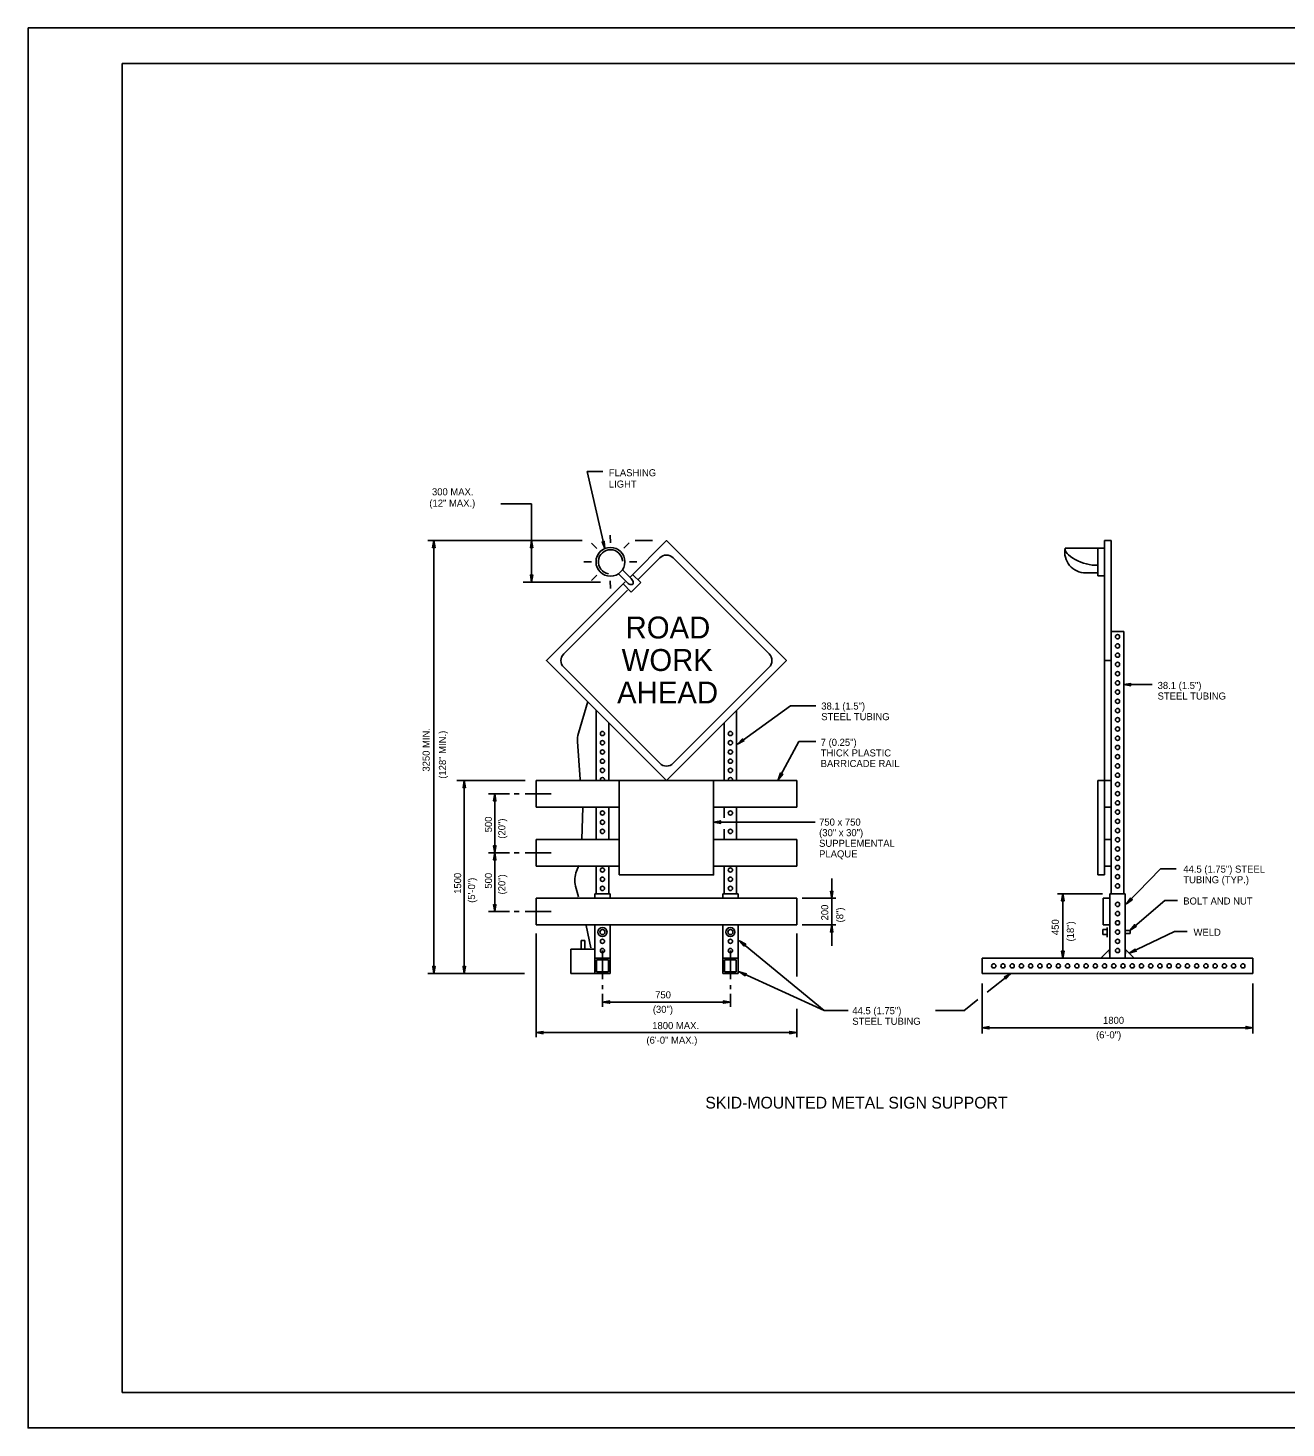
# Model space of a CAD drawing. Extents: x 641885 to 642790, y 293700 to 294294.
# Drawn here: x 641885 to 642419, y 293700 to 294294 of the extents above; entities that cross this region are included whole.
import ezdxf

# ---------------------------------------------------------------- set-up
doc = ezdxf.new("R2010")
doc.units = 0
for name, color, linetype in [('1', 7, 'Continuous'), ('2', 7, 'Continuous'), ('3', 7, 'Continuous'), ('PLT-BNDY', 7, 'Continuous')]:
    doc.layers.add(name, color=color, linetype=linetype)

# ---------------------------------------------------------------- blocks, each defined once
blk = doc.blocks.new('RARROW')
at = {"layer": '3'}
blk.add_lwpolyline([(-2.2695, 0.285), (-2.184875, 0.12075), (0, 0), (-2.2695, 0.285), (-2.38575, 0.384625), (0, 0), (-2.183125, -0.108), (-2.262875, -0.2705), (0, 0), (-2.38575, -0.379125), (-2.262875, -0.2705)], dxfattribs=at)

msp = doc.modelspace()

# ---------------------------------------------------------------- linework, layer by layer
at = {"layer": '1'}
for p, q in [((641925.31, 294278.63), (642711.31, 294278.63)), ((641925.31, 294278.63), (641925.31, 293714.63)), ((642711.31, 293714.63), (641925.31, 293714.63)), ((641925.31, 293714.63), (642511.31, 293714.63))]:
    msp.add_line(p, q, dxfattribs=at)
at = {"layer": '2'}
for p, q in [((642122.46, 294105.39), (642129.1, 294105.39)), ((642122.46, 294105.39), (642129.94, 294072.78)), ((642085.79, 294091.69), (642098.9, 294091.69)), ((642098.9, 294091.69), (642098.9, 294058.57)), ((642132.3, 294075.22), (642132.28, 294078.43)), ((642054.87, 294076.13), (642120.37, 294076.13)), ((642057.44, 293892.46), (642057.44, 294076.13)), ((642126.6, 294072.84), (642124.32, 294075.09)), ((642138.01, 294072.88), (642140.27, 294075.15)), ((642142.84, 294076.13), (642150.19, 294076.13)), ((642325.24, 294072.95), (642341.94, 294072.95)), ((642339.12, 294072.95), (642339.12, 294061.13)), ((642341.94, 294076.13), (642341.94, 293974.31)), ((642341.94, 294076.13), (642344.76, 294076.13)), ((642344.76, 294076.13), (642344.76, 293974.31)), ((642124.25, 294067.12), (642121.05, 294067.11)), ((642140.4, 294067.18), (642143.6, 294067.19)), ((642153.27, 294068.8), (642144.17, 294059.69)), ((642199.67, 294028.05), (642158.92, 294068.8)), ((642126.56, 294061.44), (642124.31, 294059.17)), ((642139.37, 294058.38), (642135.7, 294062.06)), ((642141.1, 294060.1), (642137.42, 294063.78)), ((642145.17, 294058.29), (642141.71, 294061.75)), ((642333.91, 294062.46), (642339.12, 294062.46)), ((642339.12, 294061.13), (642341.94, 294061.13)), ((642095.3, 294058.57), (642128.15, 294058.57)), ((642139.64, 294055.17), (642112.52, 294028.05)), ((642132.29, 294059.04), (642132.3, 294055.84)), ((642141.18, 294054.31), (642137.73, 294057.77)), ((642141.18, 294054.31), (642145.17, 294058.29)), ((642344.76, 294037.6), (642350.06, 294037.6)), ((642350.06, 294037.6), (642350.06, 293926.28)), ((642341.94, 294025.22), (642344.76, 294025.22)), ((642112.52, 294022.39), (642153.27, 293981.65)), ((642158.92, 293981.65), (642199.67, 294022.39)), ((642350.06, 294015.06), (642362.08, 294015.06)), ((642122.69, 294007.93), (642118.76, 293994.37)), ((642126.31, 294004.1), (642126.31, 293974.31)), ((642185.88, 294004.1), (642185.88, 293974.31)), ((642208.67, 294005.98), (642186.27, 293989.8)), ((642208.67, 294005.98), (642219.48, 294005.98)), ((642131.61, 293998.79), (642131.61, 293974.31)), ((642180.58, 293998.79), (642180.58, 293974.31)), ((642118.39, 293990.87), (642119.53, 293974.79)), ((642212.27, 293990.85), (642203.55, 293974.67)), ((642212.27, 293990.85), (642219.44, 293990.85)), ((642067.19, 293974.31), (642096.15, 293974.31)), ((642070.37, 293892.46), (642070.37, 293974.31)), ((642100.79, 293974.31), (642136.1, 293974.31)), ((642100.79, 293974.31), (642100.79, 293963)), ((642211.4, 293974.31), (642176.1, 293974.31)), ((642211.4, 293974.31), (642211.4, 293963)), ((642339.12, 293974.31), (642344.76, 293974.31)), ((642339.12, 293974.31), (642339.12, 293934.31)), ((642341.94, 293974.31), (642341.94, 293934.31)), ((642344.76, 293974.31), (642344.76, 293926.28)), ((642089.48, 293968.66), (642080.61, 293968.66)), ((642083.3, 293943.69), (642083.3, 293968.66)), ((642093.67, 293968.66), (642091.45, 293968.66)), ((642107.21, 293968.66), (642096.13, 293968.66)), ((642100.79, 293963), (642136.1, 293963)), ((642120.7, 293963), (642120.25, 293949.34)), ((642126.31, 293963), (642126.31, 293949.34)), ((642131.61, 293963), (642131.61, 293949.34)), ((642211.4, 293963), (642176.1, 293963)), ((642180.58, 293963), (642180.58, 293958.46)), ((642185.88, 293963), (642185.88, 293949.34)), ((642341.94, 293963), (642344.76, 293963)), ((642176.1, 293956.68), (642219.2, 293956.68)), ((642180.58, 293953.71), (642180.58, 293949.34)), ((642100.79, 293949.34), (642136.1, 293949.34)), ((642100.79, 293949.34), (642100.79, 293938.03)), ((642211.4, 293949.34), (642176.1, 293949.34)), ((642211.4, 293949.34), (642211.4, 293938.03)), ((642341.94, 293949.34), (642344.76, 293949.34)), ((642089.48, 293943.69), (642080.61, 293943.69)), ((642083.3, 293918.71), (642083.3, 293943.69)), ((642093.67, 293943.69), (642091.45, 293943.69)), ((642107.21, 293943.69), (642096.13, 293943.69)), ((642100.79, 293938.03), (642136.1, 293938.03)), ((642118.95, 293938.35), (642117.95, 293935.92)), ((642126.31, 293938.03), (642126.31, 293926.28)), ((642131.61, 293938.03), (642131.61, 293926.28)), ((642211.4, 293938.03), (642176.1, 293938.03)), ((642180.58, 293938.03), (642180.58, 293926.28)), ((642185.88, 293938.03), (642185.88, 293926.28)), ((642341.94, 293938.03), (642344.76, 293938.03)), ((642351.23, 293921.97), (642365.7, 293936.86)), ((642365.7, 293936.86), (642372.29, 293936.86)), ((642117.56, 293929.5), (642118.78, 293925.03)), ((642226.18, 293924.37), (642226.18, 293932.79)), ((642339.12, 293934.31), (642341.94, 293934.31)), ((642100.79, 293924.37), (642211.4, 293924.37)), ((642100.79, 293924.37), (642100.79, 293913.06)), ((642132.21, 293926.28), (642125.71, 293926.28)), ((642125.71, 293924.37), (642125.71, 293926.28)), ((642132.21, 293924.37), (642132.21, 293926.28)), ((642186.48, 293926.28), (642179.98, 293926.28)), ((642179.98, 293924.37), (642179.98, 293926.28)), ((642186.48, 293924.37), (642186.48, 293926.28)), ((642211.4, 293924.37), (642211.4, 293913.06)), ((642213.69, 293924.37), (642227.87, 293924.37)), ((642226.18, 293913.06), (642226.18, 293924.37)), ((642321.91, 293926.28), (642341.05, 293926.28)), ((642324.23, 293898.96), (642324.23, 293926.28)), ((642344.16, 293924.37), (642341.34, 293924.37)), ((642341.34, 293924.37), (642341.34, 293913.06)), ((642344.16, 293926.28), (642344.16, 293898.96)), ((642344.16, 293926.28), (642350.66, 293926.28)), ((642350.66, 293926.28), (642350.66, 293898.96)), ((642352.77, 293910.89), (642367.46, 293923.42)), ((642367.46, 293923.42), (642372.86, 293923.42)), ((642089.48, 293918.71), (642080.61, 293918.71)), ((642093.67, 293918.71), (642091.45, 293918.71)), ((642107.21, 293918.71), (642096.13, 293918.71)), ((642100.79, 293913.06), (642211.4, 293913.06)), ((642122.07, 293912.89), (642124.01, 293903.39)), ((642125.71, 293892.46), (642125.71, 293913.06)), ((642132.21, 293892.46), (642132.21, 293913.06)), ((642179.98, 293892.46), (642179.98, 293913.06)), ((642186.48, 293892.46), (642186.48, 293913.06)), ((642213.69, 293913.06), (642227.87, 293913.06)), ((642226.18, 293904.26), (642226.18, 293913.06)), ((642344.16, 293913.06), (642341.34, 293913.06)), ((642343.07, 293912.02), (642343.07, 293907.92)), ((642100.79, 293865.41), (642100.79, 293909.38)), ((642119.86, 293902.8), (642119.86, 293906.5)), ((642119.86, 293906.5), (642121.46, 293906.5)), ((642121.46, 293902.8), (642121.46, 293906.5)), ((642223, 293876.74), (642187.13, 293906.38)), ((642211.4, 293891.25), (642211.4, 293909.38)), ((642343.07, 293911.11), (642341.23, 293911.11)), ((642341.23, 293911.11), (642341.23, 293908.97)), ((642343.07, 293908.97), (642341.23, 293908.97)), ((642352.82, 293910.66), (642350.66, 293910.66)), ((642352.82, 293909.42), (642350.66, 293909.42)), ((642352.41, 293901.05), (642371.58, 293910.28)), ((642352.82, 293910.66), (642352.82, 293909.42)), ((642371.58, 293910.28), (642376.98, 293910.28)), ((642115.61, 293902.8), (642125.71, 293902.8)), ((642115.61, 293902.8), (642115.61, 293892.46)), ((642125.71, 293902.8), (642125.71, 293892.46)), ((642128.96, 293890.04), (642128.96, 293902.21)), ((642183.23, 293890.04), (642183.23, 293902.21)), ((642132.21, 293898.96), (642125.71, 293898.96)), ((642126.46, 293893.21), (642126.46, 293898.21)), ((642131.46, 293898.21), (642126.46, 293898.21)), ((642131.46, 293893.21), (642131.46, 293898.21)), ((642186.48, 293898.96), (642179.98, 293898.96)), ((642180.73, 293893.21), (642180.73, 293898.21)), ((642185.73, 293898.21), (642180.73, 293898.21)), ((642185.73, 293893.21), (642185.73, 293898.21)), ((642289.96, 293898.96), (642404.86, 293898.96)), ((642289.96, 293898.96), (642289.96, 293892.46)), ((642404.86, 293898.96), (642404.86, 293892.46)), ((642054.87, 293892.46), (642095.88, 293892.46)), ((642115.61, 293892.46), (642125.71, 293892.46)), ((642132.21, 293892.46), (642125.71, 293892.46)), ((642131.46, 293893.21), (642126.46, 293893.21)), ((642128.96, 293885.8), (642128.96, 293887.52)), ((642186.48, 293892.46), (642179.98, 293892.46)), ((642185.73, 293893.21), (642180.73, 293893.21)), ((642183.23, 293885.8), (642183.23, 293887.52)), ((642223, 293876.74), (642187.02, 293893.19)), ((642289.96, 293892.46), (642404.86, 293892.46)), ((642289.96, 293867.01), (642289.96, 293888.2)), ((642292.13, 293884.57), (642302.1, 293892.46)), ((642404.86, 293867.01), (642404.86, 293888.2)), ((642128.96, 293878.34), (642128.96, 293883.89)), ((642183.23, 293878.34), (642183.23, 293883.89)), ((642128.96, 293880.31), (642183.23, 293880.31)), ((642211.4, 293865.41), (642211.4, 293877.44)), ((642223, 293876.74), (642233.15, 293876.74)), ((642270.25, 293876.74), (642282.25, 293876.74)), ((642282.18, 293876.69), (642288.11, 293881.38)), ((642100.79, 293867.38), (642211.4, 293867.38)), ((642289.96, 293869.48), (642404.86, 293869.48))]:
    msp.add_line(p, q, dxfattribs=at)
msp.add_lwpolyline([(642138.62, 294058.66), (642105.18, 294025.22), (642156.1, 293974.31), (642207.01, 294025.22), (642156.1, 294076.13), (642140.65, 294060.69)], dxfattribs=at)
for points in [[(642136.1, 293934.31), (642176.1, 293934.31), (642176.1, 293974.31), (642136.1, 293974.31)], [(642344.16, 293898.96), (642340.33, 293898.91), (642344.02, 293902.61)], [(642350.66, 293898.96), (642354.49, 293898.91), (642350.79, 293902.61)]]:
    msp.add_lwpolyline(points, close=True, dxfattribs=at)
for centre, radius in [((642132.33, 294067.15), 6.11), ((642347.41, 294035.36), 0.903), ((642347.41, 294031.44), 0.903), ((642347.41, 294027.52), 0.903), ((642347.41, 294023.61), 0.903), ((642347.41, 294019.69), 0.903), ((642347.41, 294015.77), 0.903), ((642347.41, 294011.86), 0.903), ((642347.41, 294007.94), 0.903), ((642347.41, 294004.03), 0.903), ((642347.41, 294000.11), 0.903), ((642128.96, 293994.29), 0.903), ((642183.23, 293994.29), 0.903), ((642347.41, 293996.19), 0.903), ((642128.96, 293990.38), 0.903), ((642183.23, 293990.38), 0.903), ((642347.41, 293992.28), 0.903), ((642347.41, 293988.36), 0.903), ((642128.96, 293986.46), 0.903), ((642128.96, 293982.54), 0.903), ((642183.23, 293986.46), 0.903), ((642183.23, 293982.54), 0.903), ((642347.41, 293984.45), 0.903), ((642128.96, 293978.63), 0.903), ((642183.23, 293978.63), 0.903), ((642347.41, 293980.53), 0.903), ((642347.41, 293976.61), 0.903), ((642347.41, 293972.7), 0.903), ((642347.41, 293968.78), 0.903), ((642347.41, 293964.87), 0.903), ((642128.96, 293960.56), 0.903), ((642183.23, 293960.56), 0.903), ((642347.41, 293960.95), 0.903), ((642128.96, 293956.65), 0.903), ((642128.96, 293952.73), 0.903), ((642183.23, 293952.73), 0.903), ((642347.41, 293957.03), 0.903), ((642347.41, 293953.12), 0.903), ((642347.41, 293949.2), 0.903), ((642347.41, 293945.28), 0.903), ((642347.41, 293941.37), 0.903), ((642128.96, 293936.39), 0.903), ((642183.23, 293936.39), 0.903), ((642347.41, 293937.45), 0.903), ((642128.96, 293932.47), 0.903), ((642128.96, 293928.56), 0.903), ((642183.23, 293932.47), 0.903), ((642183.23, 293928.56), 0.903), ((642347.41, 293933.54), 0.903), ((642347.41, 293929.62), 0.903), ((642347.41, 293921.79), 0.903), ((642347.41, 293917.87), 0.903), ((642128.96, 293910.04), 1.93), ((642183.23, 293910.04), 1.93), ((642347.41, 293913.96), 0.903), ((642128.96, 293910.04), 1.07), ((642128.96, 293906.12), 0.903), ((642183.23, 293910.04), 1.07), ((642183.23, 293906.12), 0.903), ((642347.41, 293910.04), 0.903), ((642347.41, 293906.12), 0.903), ((642128.96, 293902.21), 0.903), ((642183.23, 293902.21), 0.903), ((642347.41, 293902.21), 0.903), ((642294.91, 293895.71), 0.903), ((642298.83, 293895.71), 0.903), ((642302.74, 293895.71), 0.903), ((642306.66, 293895.71), 0.903), ((642310.58, 293895.71), 0.903), ((642314.49, 293895.71), 0.903), ((642318.41, 293895.71), 0.903), ((642322.32, 293895.71), 0.903), ((642326.24, 293895.71), 0.903), ((642330.16, 293895.71), 0.903), ((642334.07, 293895.71), 0.903), ((642337.99, 293895.71), 0.903), ((642341.9, 293895.71), 0.903), ((642345.82, 293895.71), 0.903), ((642349.74, 293895.71), 0.903), ((642353.65, 293895.71), 0.903), ((642357.57, 293895.71), 0.903), ((642361.49, 293895.71), 0.903), ((642365.4, 293895.71), 0.903), ((642369.32, 293895.71), 0.903), ((642373.23, 293895.71), 0.903), ((642377.07, 293895.71), 0.903), ((642380.99, 293895.71), 0.903), ((642384.9, 293895.71), 0.903), ((642388.82, 293895.71), 0.903), ((642392.74, 293895.71), 0.903), ((642396.65, 293895.71), 0.903), ((642400.57, 293895.71), 0.903)]:
    msp.add_circle(centre, radius, dxfattribs=at)
for centre, radius, start, end in [((642132.33, 294067.15), 5.12, 2.99859, 260.92051), ((642333.79, 294071.19), 8.73, 168.39588, 270.8338), ((642156.1, 294065.97), 4, 44.99999, 135), ((642115.35, 294025.22), 4, 135, 225), ((642196.84, 294025.22), 4, 314.99967, 44.99998), ((642128.36, 293991.58), 10, 163.81078, 184.07684), ((642156.1, 293984.48), 4, 224.99984, 315.0003), ((642128.96, 293974.71), 0.903, 350.18245, 189.46844), ((642183.23, 293974.71), 0.903, 350.53156, 189.81755), ((642127.21, 293932.13), 10, 157.72787, 195.25958)]:
    msp.add_arc(centre, radius, start, end, dxfattribs=at)
for centre, major_axis, ratio, start_param, end_param in [((642333.25, 294069.93), (8.01, -3.02), 0.375725, 3.141593, 5.588182), ((642140.23, 294059.24), (1.54, -1.54), 0.560008, 4.712389, 7.853982)]:
    msp.add_ellipse(centre, major_axis=major_axis, ratio=ratio, start_param=start_param, end_param=end_param, dxfattribs=at)
at = {"layer": 'PLT-BNDY'}
msp.add_lwpolyline([(641885.31, 294293.63), (642726.31, 294293.63), (642726.31, 293699.63), (641885.31, 293699.63)], close=True, dxfattribs=at)

# ---------------------------------------------------------------- block references
at = {"layer": '2'}
for p, xscale, yscale, rotation in [((642057.44, 294076.13), 1.2574347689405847, 1.3092961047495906, 89.99999999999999), ((642098.9, 294076.13), 1.2574347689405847, 1.3092961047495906, 89.99999999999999), ((642129.94, 294072.78), 1.257434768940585, 1.3092961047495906, -76.65647202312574), ((642098.9, 294058.57), 1.2574347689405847, 1.3092961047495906, -90.00000000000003), ((642350.06, 294015.06), 1.2574347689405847, 1.3092961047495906, 180), ((642186.26, 293989.8), 1.257434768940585, 1.3092961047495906, -143.95284350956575), ((642203.55, 293974.67), 1.2574347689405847, 1.3092961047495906, -118.29722389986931), ((642070.37, 293974.31), 1.2574347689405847, 1.3092961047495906, 89.99999999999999), ((642083.3, 293968.66), 1.2574347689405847, 1.3092961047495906, 89.99999999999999), ((642176.1, 293956.68), 1.2574347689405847, 1.3092961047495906, 180), ((642083.3, 293943.69), 1.2574347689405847, 1.3092961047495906, -90.00000000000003), ((642083.3, 293943.69), 1.2574347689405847, 1.3092961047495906, 89.99999999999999), ((642226.18, 293924.37), 1.2574347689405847, 1.3092961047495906, -90.00000000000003), ((642324.22, 293926.28), 1.2574347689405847, 1.3092961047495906, 89.99999999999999), ((642351.23, 293921.97), 1.2574347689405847, 1.3092961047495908, -134.20874209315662), ((642083.3, 293918.72), 1.2574347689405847, 1.3092961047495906, -90.00000000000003), ((642226.18, 293913.06), 1.2574347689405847, 1.3092961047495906, 89.99999999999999), ((642352.77, 293910.89), 1.2574347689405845, 1.3092961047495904, -139.54557767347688), ((642187.13, 293906.38), 1.2574347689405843, 1.3092961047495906, 140.2360200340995), ((642324.22, 293898.96), 1.2574347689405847, 1.3092961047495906, -90.00000000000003), ((642352.41, 293901.05), 1.2574347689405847, 1.3092961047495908, -154.2997184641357), ((642057.44, 293892.46), 1.2574347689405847, 1.3092961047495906, -90.00000000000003), ((642070.37, 293892.46), 1.2574347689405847, 1.3092961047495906, -90.00000000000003), ((642187.02, 293893.19), 1.2574347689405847, 1.3092961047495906, 155.22886209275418), ((642302.1, 293892.46), 1.257434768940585, 1.3092961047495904, 38.5772109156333), ((642128.96, 293880.31), 1.2574347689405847, 1.3092961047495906, 180), ((642289.96, 293869.48), 1.2574347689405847, 1.3092961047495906, 180), ((642100.79, 293867.38), 1.2574347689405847, 1.3092961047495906, 180)]:
    msp.add_blockref('RARROW', p, dxfattribs=dict(at, xscale=xscale, yscale=yscale, rotation=rotation))
at = {"layer": '2', "xscale": 1.2574347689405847, "yscale": 1.3092961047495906}
for p in [(642183.23, 293880.31), (642404.86, 293869.48), (642211.4, 293867.38)]:
    msp.add_blockref('RARROW', p, dxfattribs=at)

# ---------------------------------------------------------------- texts
at = {"layer": '2'}
for s, height, p in [('FLASHING', 3, (642131.66, 294103.43)), ('LIGHT', 3, (642131.66, 294098.63)), (' 300 MAX.', 3, (642055.53, 294095.34)), ('(12" MAX.)', 3, (642055.53, 294090.54)), ('ROAD', 9.301, (642138.76, 294034.61)), ('WORK', 9.301, (642137.1, 294020.83)), ('AHEAD', 9.301, (642135.15, 294007.05)), ('38.1 (1.5")', 3, (642364.42, 294013.19)), ('38.1 (1.5")', 3, (642221.76, 294004.44)), ('STEEL TUBING', 3, (642364.42, 294008.69)), ('STEEL TUBING', 3, (642221.76, 293999.94)), ('7 (0.25")', 3, (642221.52, 293989.05)), ('THICK PLASTIC', 3, (642221.52, 293984.55)), ('BARRICADE RAIL', 3, (642221.52, 293980.05)), ('750 x 750', 3, (642220.85, 293955.21)), ('(30" x 30")', 3, (642220.85, 293950.71)), ('SUPPLEMENTAL', 3, (642220.85, 293946.21)), ('PLAQUE', 3, (642220.85, 293941.71)), ('44.5 (1.75") STEEL', 3, (642375.31, 293935.26)), ('TUBING (TYP.)', 3, (642375.31, 293930.76)), ('BOLT AND NUT', 3, (642375.29, 293921.72)), ('WELD', 3, (642379.65, 293908.46)), ('750', 3, (642151.31, 293881.92)), ('(30")', 3, (642150.32, 293875.76)), ('44.5 (1.75")', 3, (642234.93, 293875.2)), ('1800 MAX.', 3, (642150.08, 293868.86)), ('STEEL TUBING', 3, (642234.93, 293870.7)), ('1800', 3, (642341.27, 293871.08)), ('(6\'-0" MAX.)', 3, (642147.61, 293862.7)), ('(6\'-0")', 3, (642338.31, 293864.92)), ('SKID-MOUNTED METAL SIGN SUPPORT', 5, (642172.6, 293835.17))]:
    msp.add_text(s, height=height, dxfattribs=at).set_placement(p)
for s, p in [('3250 MIN.', (642055.67, 293978.12)), ('(128" MIN.)', (642062.59, 293975.1)), ('500', (642082.09, 293952.37)), ('(20")', (642087.75, 293949.66)), ('1500', (642069.03, 293926.26)), ('500', (642082.09, 293928.47)), ('(5\'-0")', (642074.94, 293922.45)), ('(20")', (642087.75, 293926.01)), ('200', (642224.72, 293914.99)), ('(8")', (642231.12, 293914.13)), ('450', (642322.52, 293908.77)), ('(18")', (642328.92, 293906.06))]:
    msp.add_text(s, height=3, rotation=90, dxfattribs=at).set_placement(p)

doc.saveas('drawing.dxf')
